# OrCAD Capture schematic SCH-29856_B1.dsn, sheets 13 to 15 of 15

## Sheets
13 15 MISC: size C
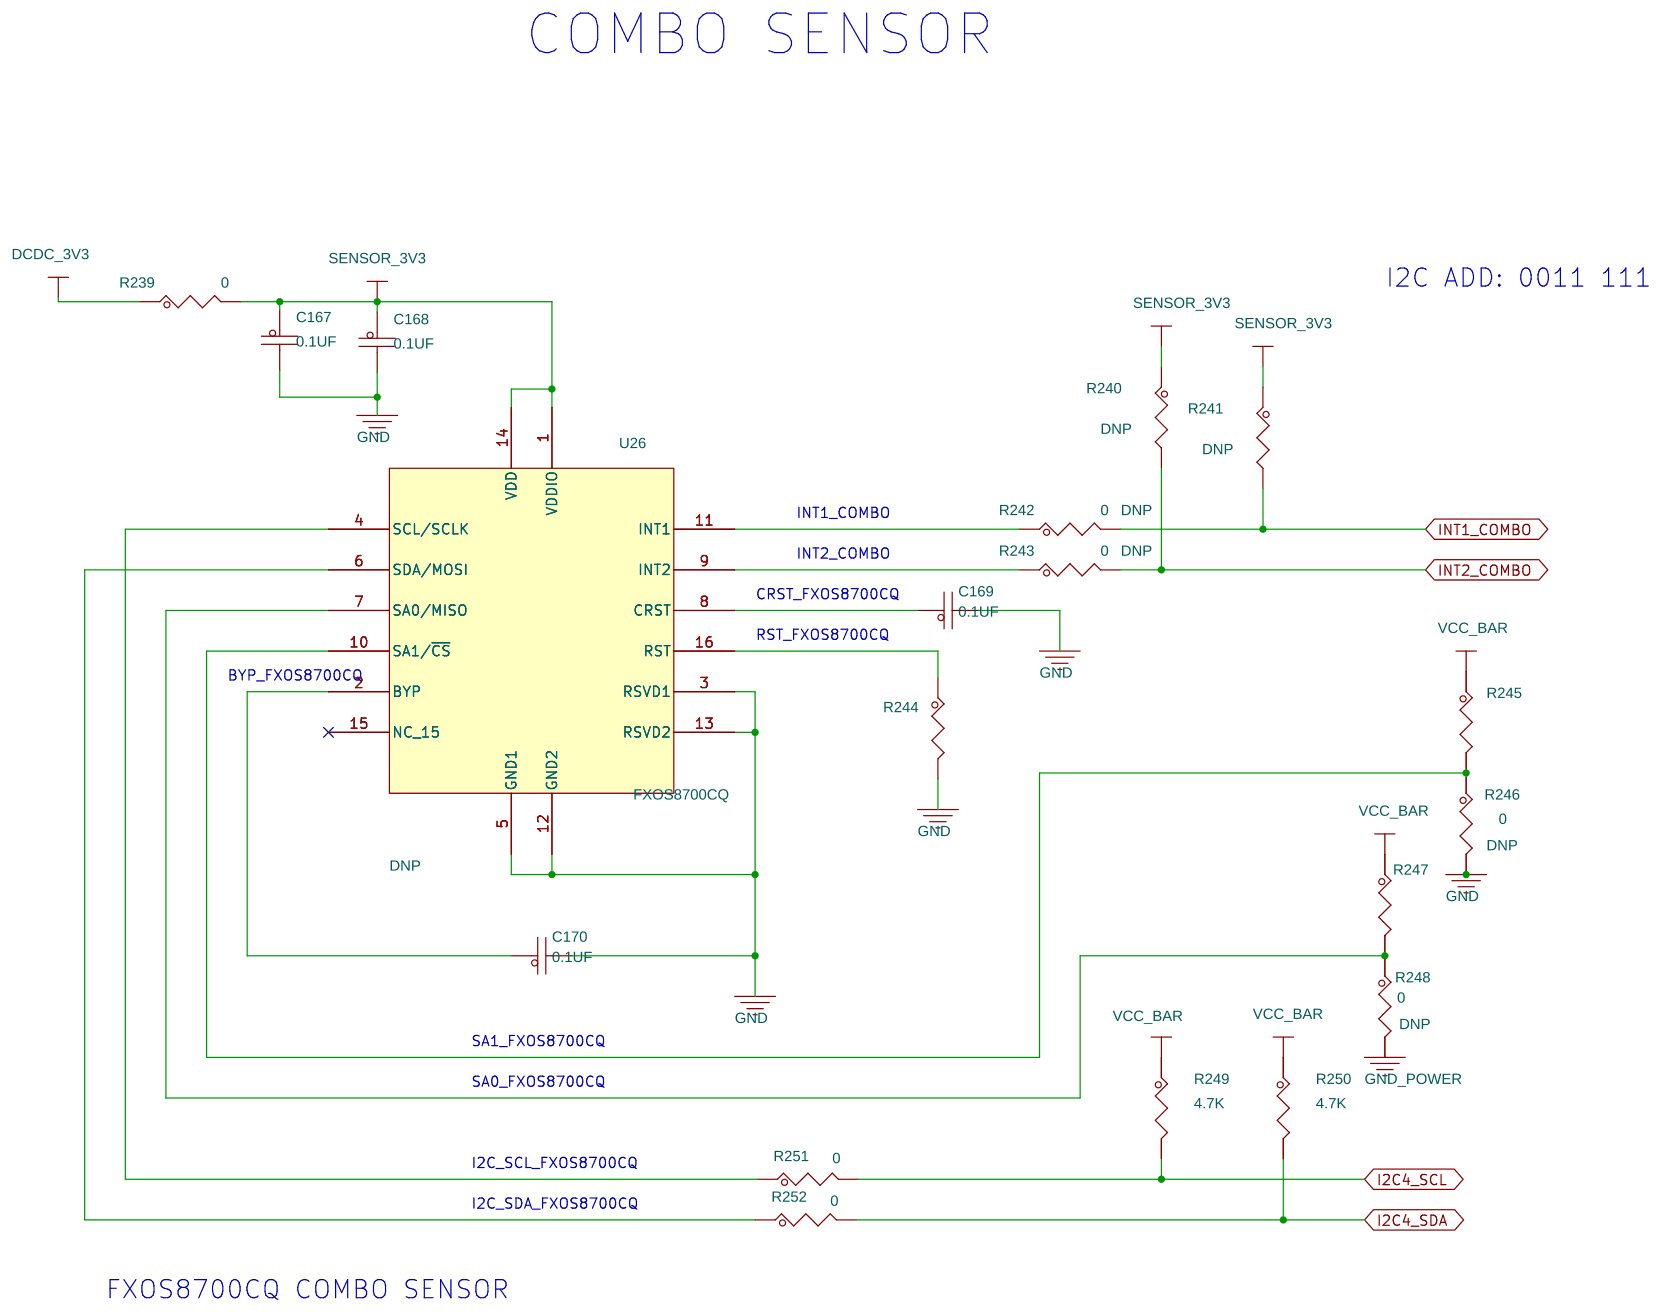
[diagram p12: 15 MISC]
14 10 SD/FLASH: size C
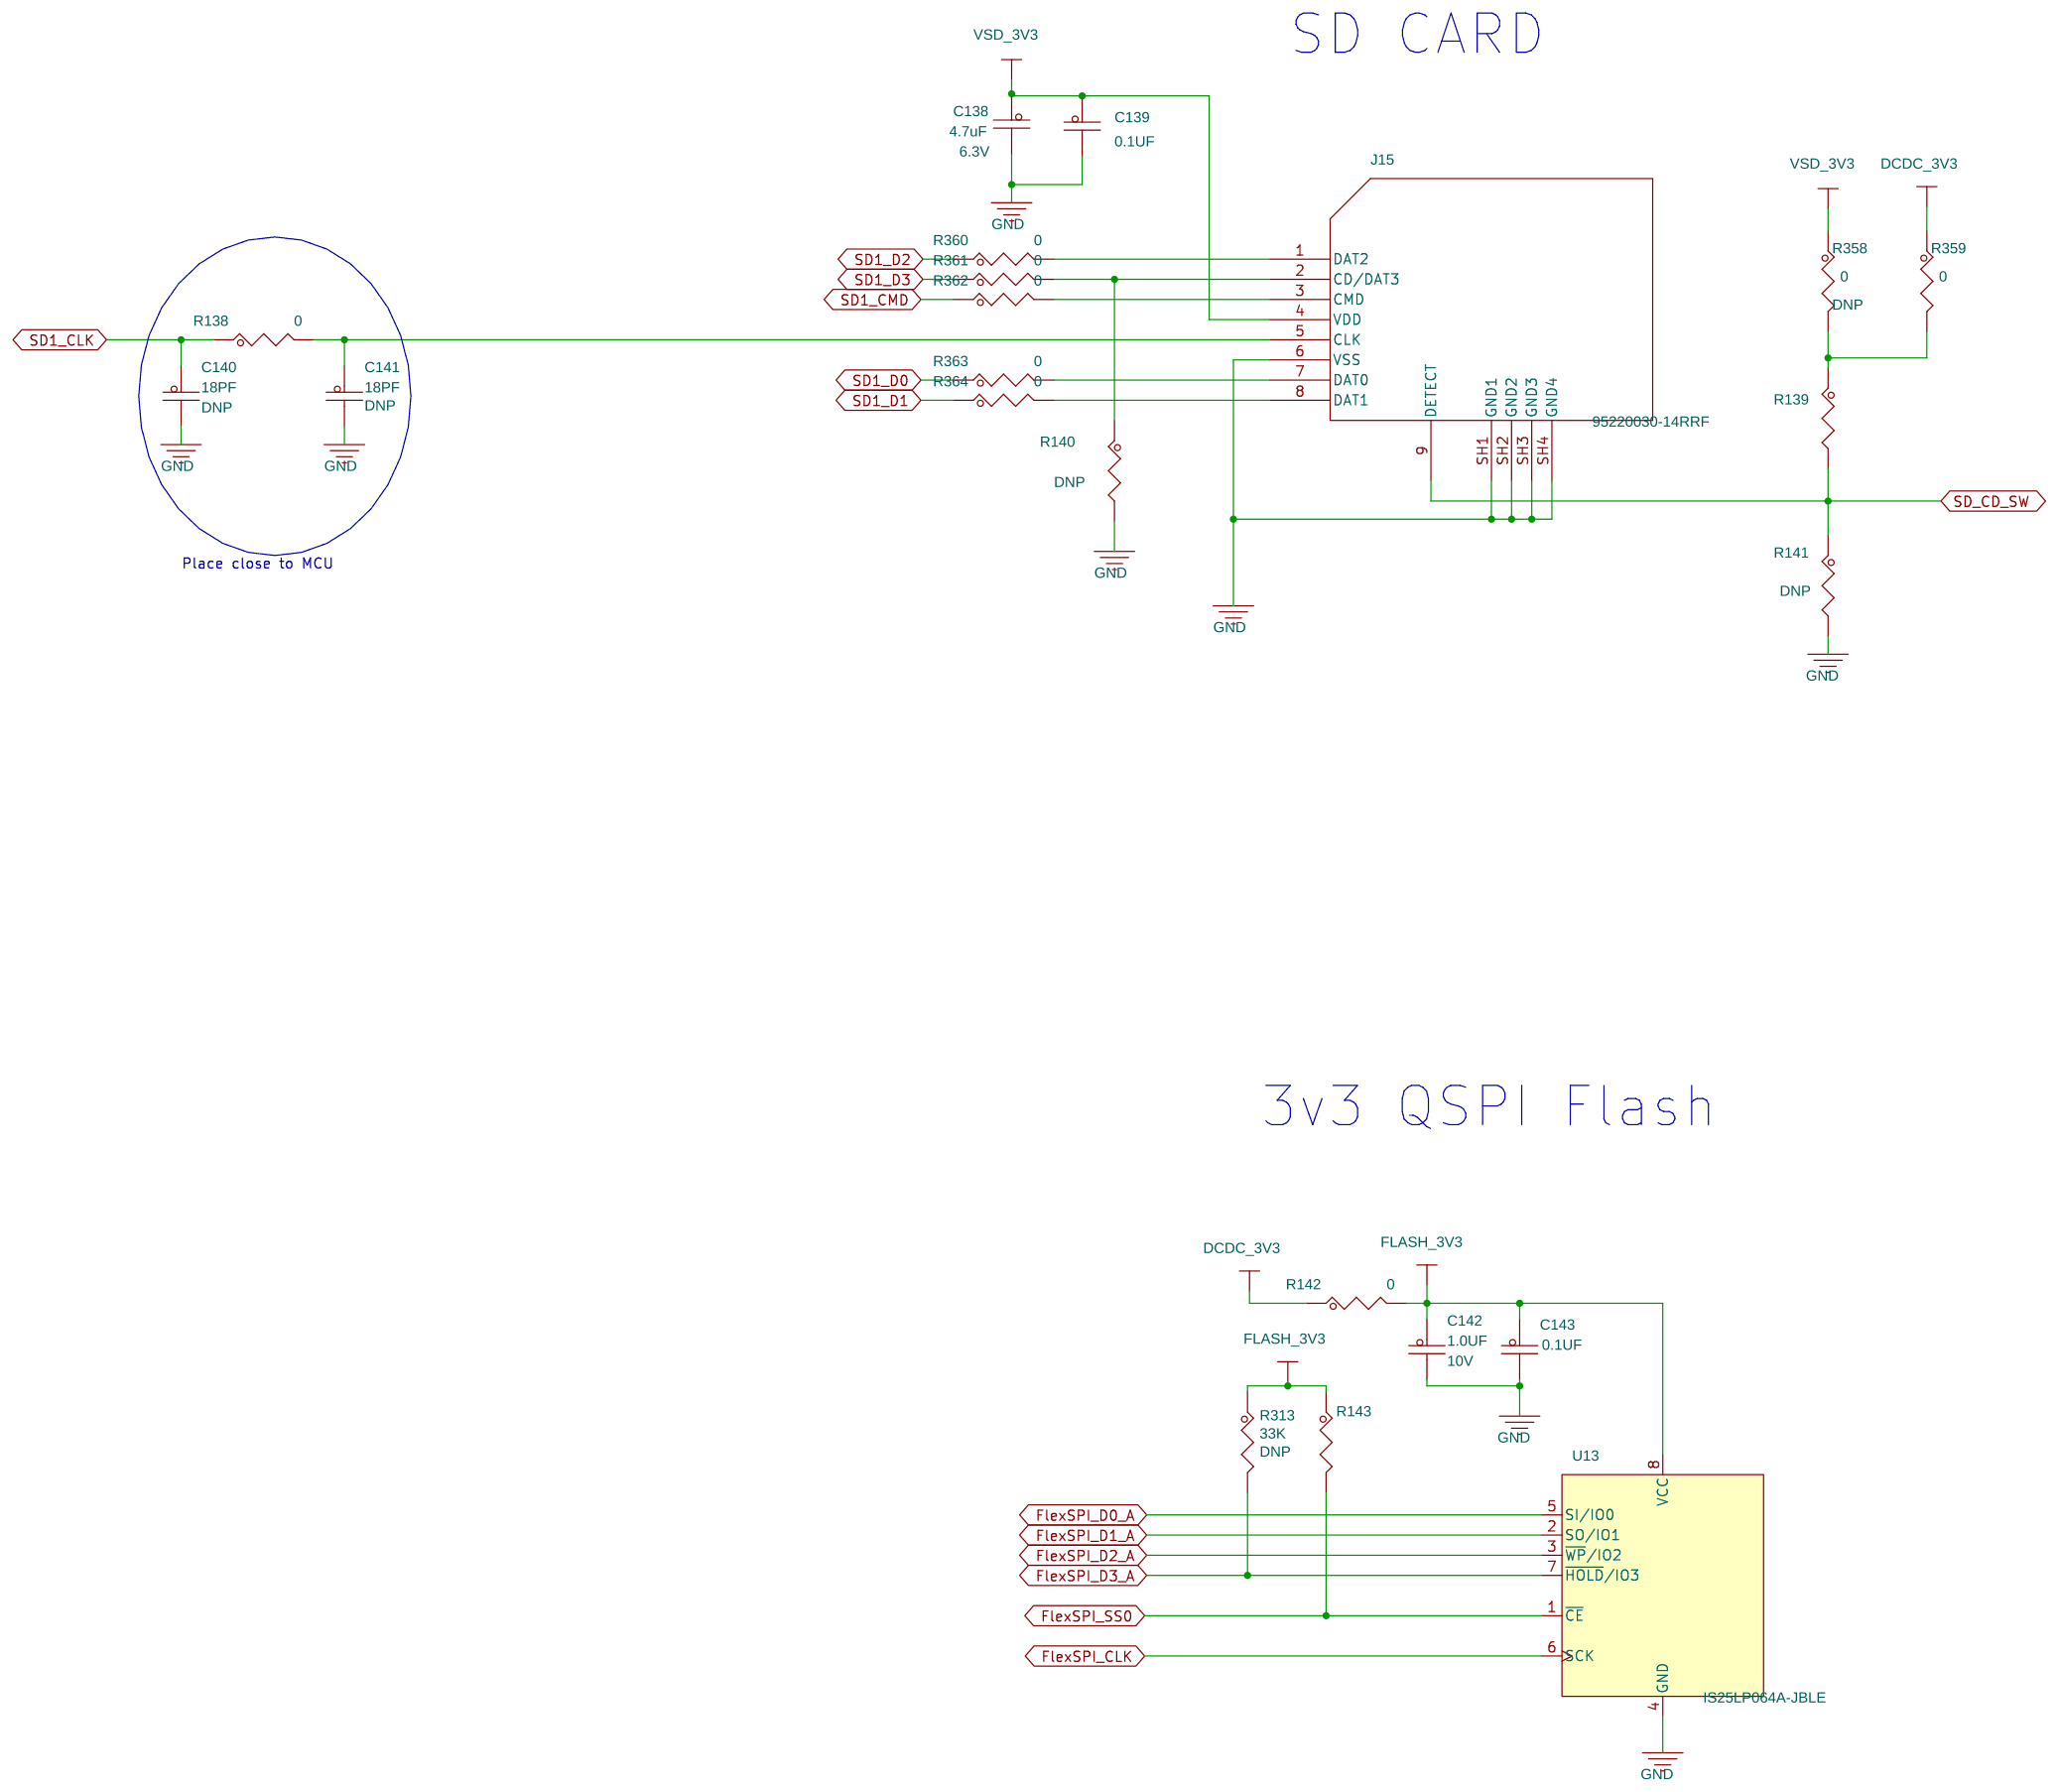
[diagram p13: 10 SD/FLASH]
15 11 ARDUINO/JTAG: size C
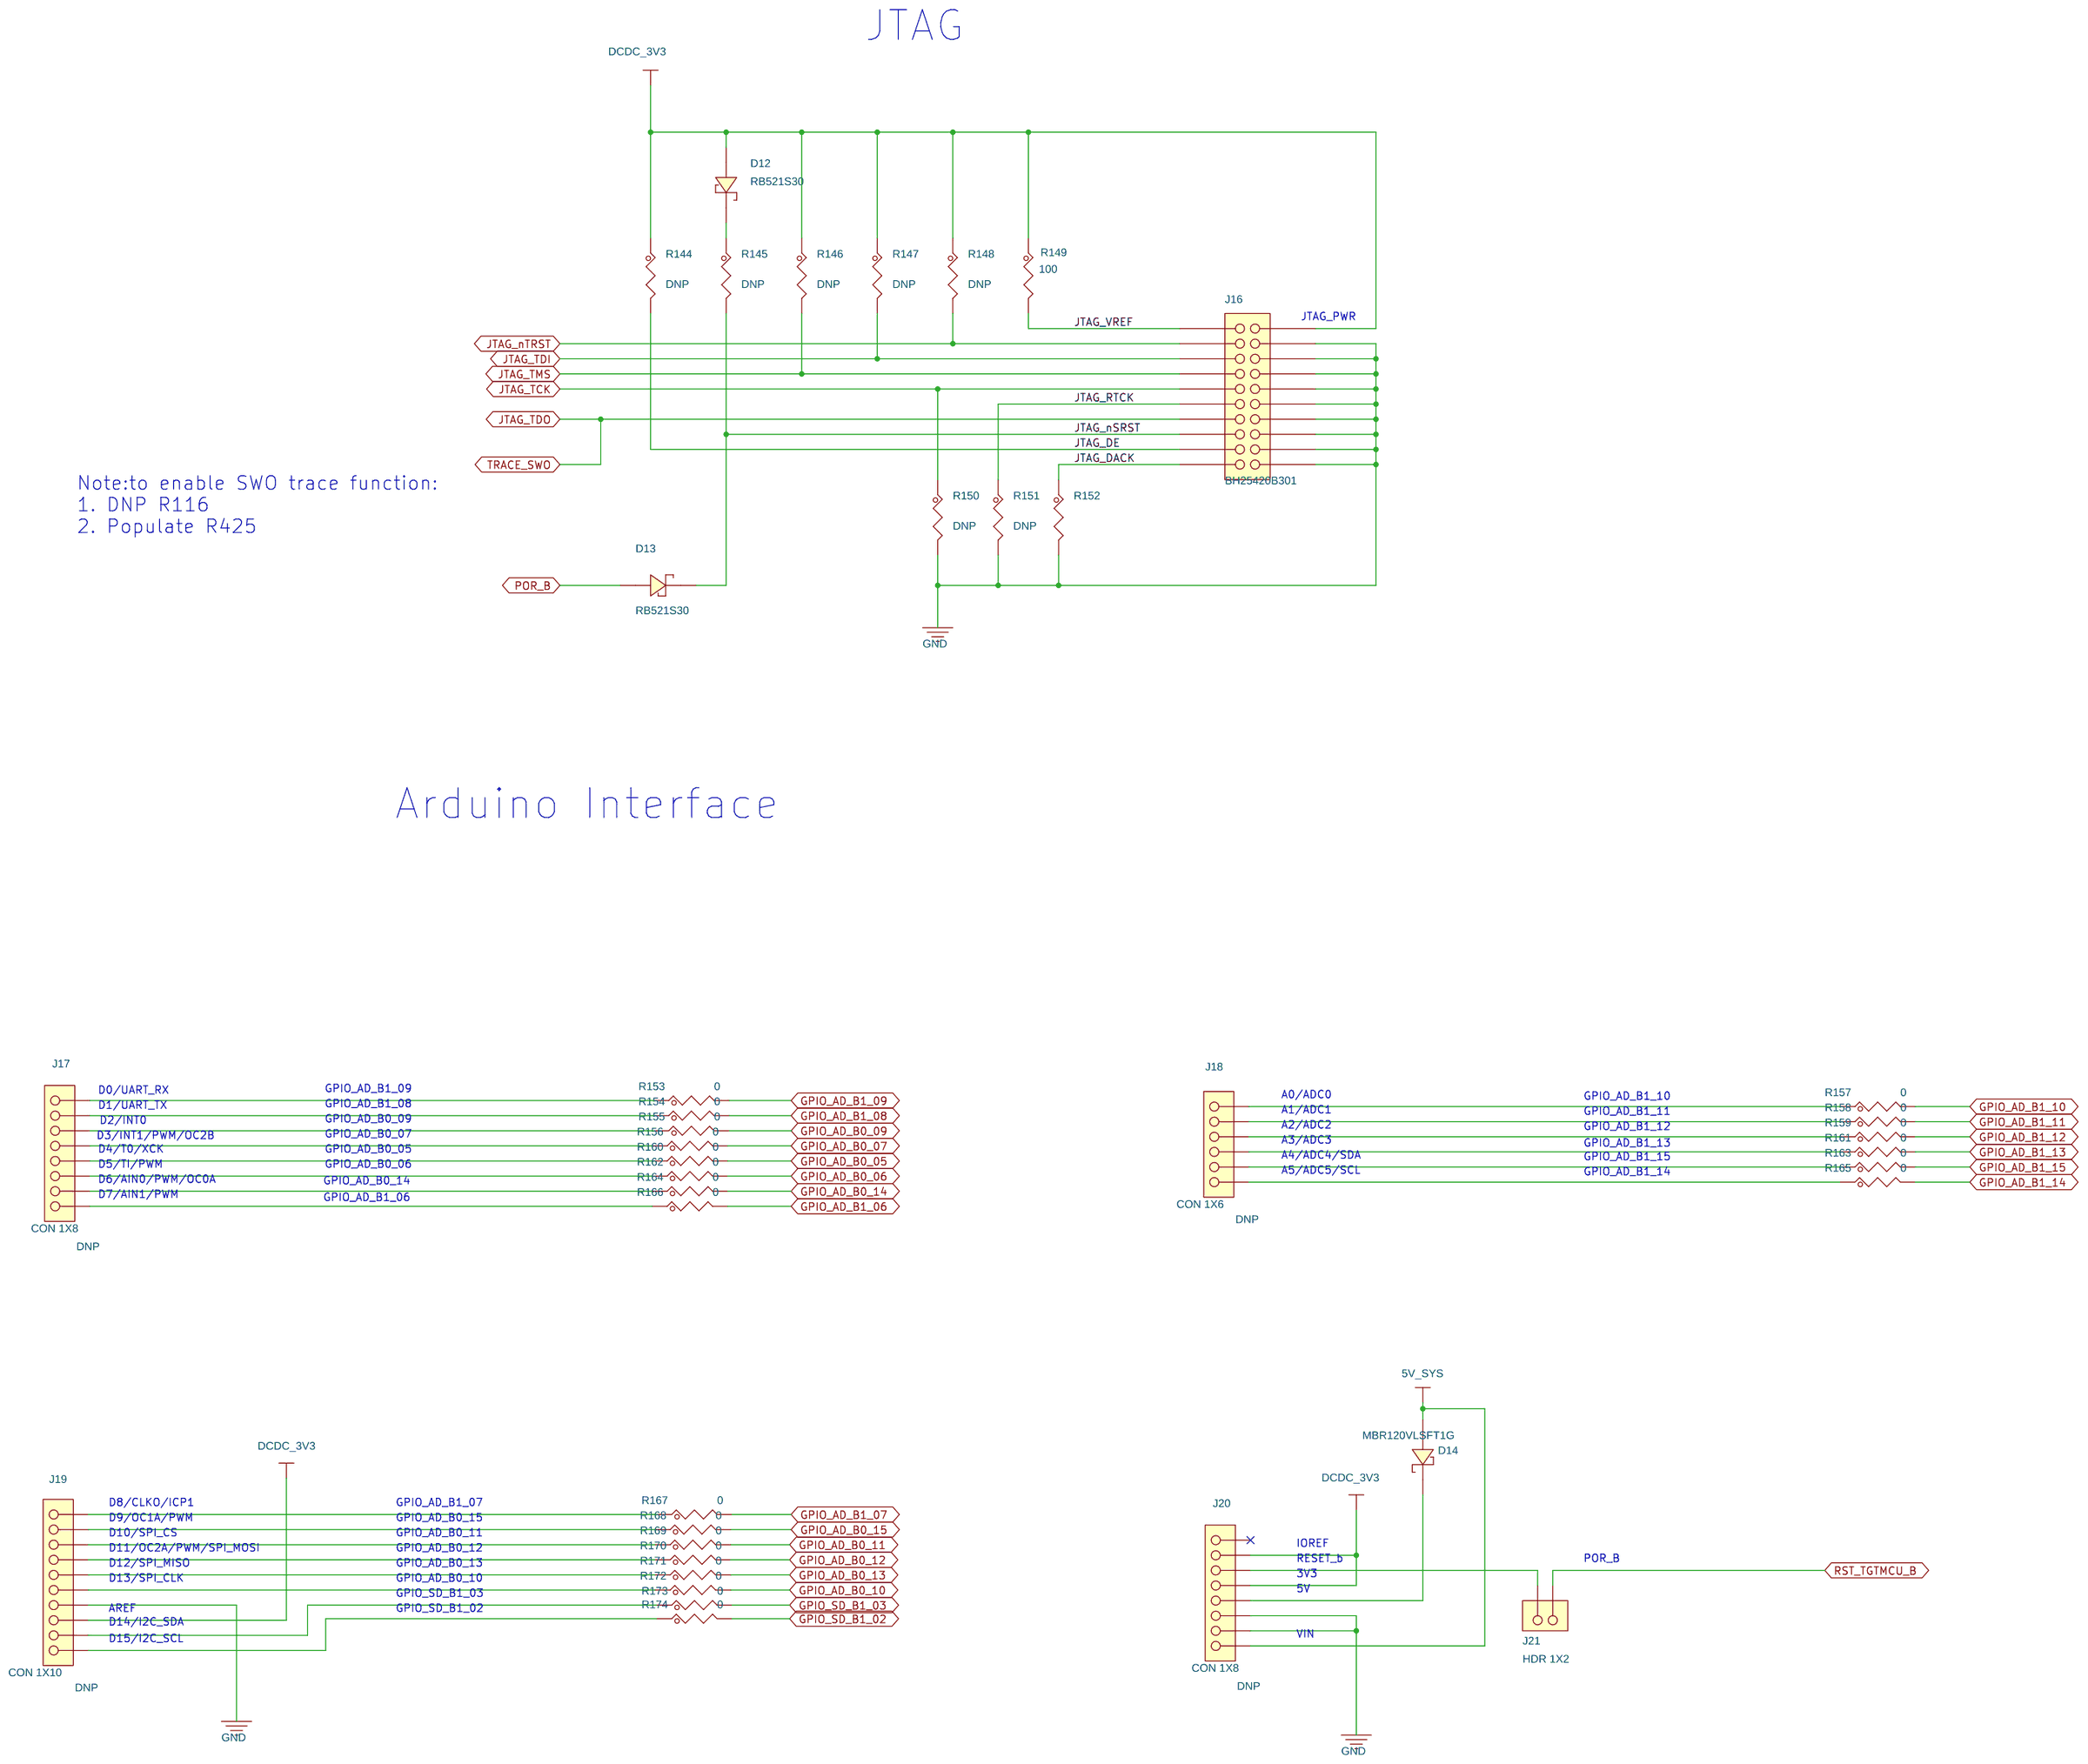
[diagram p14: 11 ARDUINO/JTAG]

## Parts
sheet 10 SD/FLASH
C138  4.7uF  [0402_CC]
C139  0.1UF  [CC0402_25]
C140  18PF  [0402_CC]
C141  18PF  [0402_CC]
C142  1.0UF  [0402_CC]
C143  0.1UF  [CC0402_25]
J15  95220030-14RRF  [CON_SDCARD_95220]
R138  0  [0402_CC]
R139  10K  [0402_CC]
R140  10K  [0402_CC]
R141  10K  [0402_CC]
R142  0  [0402_CC]
R143  10K  [0402_CC]
R313  33K  [RC0402_25]
R358  0  [0402_CC]
R359  0  [0402_CC]
R360  0  [0402_CC]
R361  0  [0402_CC]
R362  0  [0402_CC]
R363  0  [0402_CC]
R364  0  [0402_CC]
U13  IS25LP064A-JBLE  [so8_w]
sheet 11 ARDUINO/JTAG
D12  RB521S30  [SOD523]
D13  RB521S30  [SOD523]
D14  MBR120VLSFT1G  [SOD-123]
J16  BH25420B301  [hdr_2x10m_100_th]
J17  CON 1X8  [con_skt1x8_th]
J18  CON 1X6  [con_skt1x6_th]
J19  CON 1X10  [con_skt1x10_th]
J20  CON 1X8  [con_skt1x8_th]
J21  HDR 1X2  [HDR102]
R144  10K  [0402_CC]
R145  10K  [0402_CC]
R146  10K  [0402_CC]
R147  10K  [0402_CC]
R148  10K  [0402_CC]
R149  100  [0402_CC]
R150  10K  [0402_CC]
R151  10K  [0402_CC]
R152  10K  [0402_CC]
R153  0  [0402_CC]
R154  0  [0402_CC]
R155  0  [0402_CC]
R156  0  [0402_CC]
R157  0  [0402_CC]
R158  0  [0402_CC]
R159  0  [0402_CC]
R160  0  [0402_CC]
R161  0  [0402_CC]
R162  0  [0402_CC]
R163  0  [0402_CC]
R164  0  [0402_CC]
R165  0  [0402_CC]
R166  0  [0402_CC]
R167  0  [0402_CC]
R168  0  [0402_CC]
R169  0  [0402_CC]
R170  0  [0402_CC]
R171  0  [0402_CC]
R172  0  [0402_CC]
R173  0  [0402_CC]
R174  0  [0402_CC]
sheet 15 MISC
C167  0.1UF  [CC0402_25]
C168  0.1UF  [CC0402_25]
C169  0.1UF  [CC0402_25]
C170  0.1UF  [CC0402_25]
R239  0  [0402_CC]
R240  10K  [0402_CC]
R241  10K  [0402_CC]
R242  0  [0402_CC]
R243  0  [0402_CC]
R244  10K  [0402_CC]
R245  10K  [0402_CC]
R246  0  [0402_CC]
R247  10K  [0402_CC]
R248  0  [0402_CC]
R249  4.7K  [RC0402_25]
R250  4.7K  [RC0402_25]
R251  0  [0402_CC]
R252  0  [0402_CC]
U26  FXOS8700CQ  [QFN5X3_0P5_3X3]

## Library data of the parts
C138 = CAP_NP: CAP CER 4.7UF 6.3V 20% X5R 0402; AGILE_PN: 150-78463; CAD_APPROVED: Yes; FPLIST: CC0402_25,CC0402_HD,0402_CC; HEIGHT: 0.65MM; MFG_NAME01: TDK; MFG_PN01: C1005X5R0J475M050BC; ROHS: Yes; Tolerance: 20%; VOLTAGE: 6.3V; voltage rating: 6.3V
C139 C143 C167-C170 = CAP_NP: CAP CER 0.1UF 10V 10% X5R 0402; AGILE_PN: 150-75634; CAD_APPROVED: Yes; FPLIST: CC0402_25,CC0402_HD,0402_CC; HEIGHT: 0.64MM; MFG_NAME01: KEMET; MFG_PN01: C0402C104K8PAC; ROHS: Yes; Tolerance: 10%; VOLTAGE: 10V
C140 C141 = CAP_NP: CAP CER 18PF 50V 1% C0G 0402; AGILE_PN: 150-76630; ASSY_OPT: DNP; CAD_APPROVED: Yes; FPLIST: CC0402_25,CC0402_HD,0402_CC; HEIGHT: 0.59MM; MFG_NAME01: YAGEO; MFG_PN01: CC0402FRNPO9BN180; PRIORITY_PN: 021-00248; ROHS: Yes; ROOM: ATLAS-AP; Tolerance: 1%; VOLTAGE: 50V
C142 = CAP_NP: CAP CER 1.0UF 10V 10% X5R 0402; AGILE_PN: 150-75772; CAD_APPROVED: Yes; FPLIST: CC0402_25,CC0402_HD,0402_CC; HEIGHT: 0.6MM; MFG_NAME01: YAGEO AMERICA; MFG_PN01: CC0402KRX5R6BB105; ROHS: Yes; VOLTAGE: 10V; voltage rating: 10V
J15 = CON8_SDCARD_DETECT: CON 8 SKT SD/MMC RA SMT 43MIL SP 84H AU; AGILE_PN: 211-80169; CAD_APPROVED: Yes; HEIGHT: 2.13MM; MFG_NAME01: ANYTRONIC CORPORATION LIMITED; ROHS: Yes; Temp_Range: -25C to +85C
R138 R142 R153-R174 R239 R251 R252 R359-R364 = RES: RES MF ZERO OHM 1/16W 5% 0402; AGILE_PN: 470-75394; CAD_APPROVED: Yes; FPLIST: RC0402_25,RC0402_HD,RC0402_X2,0402_CC; HEIGHT: 0.45 MM; MFG_NAME01: ROHM; MFG_PN01: MCR01MZPJ000; ROHS: Yes; Tolerance: 5%
R139 R143 = RES: RES MF 10K 1/16W 5% 0402; AGILE_PN: 470-75557; CAD_APPROVED: Yes; FPLIST: RC0402_25,RC0402_HD,0402_CC; HEIGHT: 0.4 MM; MFG_NAME01: VISHAY INTERTECHNOLOGY; MFG_PN01: CRCW040210K0JNED; ROHS: Yes; TOL: 5%; Tolerance: 5%
R140 R144-R148 R150 R151 R240 R241 = RES: RES MF 10K 1/16W 5% 0402; AGILE_PN: 470-75557; ASSY_OPT: DNP; CAD_APPROVED: Yes; FPLIST: RC0402_25,RC0402_HD,0402_CC; HEIGHT: 0.4 MM; MFG_NAME01: VISHAY INTERTECHNOLOGY; MFG_PN01: CRCW040210K0JNED; ROHS: Yes; Tolerance: 5%
R141 = RES: RES MF 10K 1/16W 5% 0402; AGILE_PN: 470-75557; ASSY_OPT: DNP; CAD_APPROVED: Yes; FPLIST: RC0402_25,RC0402_HD,0402_CC; HEIGHT: 0.4 MM; MFG_NAME01: VISHAY INTERTECHNOLOGY; MFG_PN01: CRCW040210K0JNED; ROHS: Yes; TOL: 5%; Tolerance: 5%
R313 = RES: RES MF 33K  1/16W 1% 0402; AGILE_PN: 470-31004; ASSY_OPT: DNP; CAD_APPROVED: Yes; FPLIST: RC0402_25,RC0402_HD,0402_CC; HEIGHT: 0.40 MM; MFG_NAME01: YAGEO AMERICA; MFG_PN01: RC0402FR-0733KL; ROHS: Yes; Temp_Range: -55°C ~ 155°C; Tolerance: 1%
R242 R243 R246 R248 R358 = RES: RES MF ZERO OHM 1/16W 5% 0402; AGILE_PN: 470-75394; ASSY_OPT: DNP; CAD_APPROVED: Yes; FPLIST: RC0402_25,RC0402_HD,RC0402_X2,0402_CC; HEIGHT: 0.45 MM; MFG_NAME01: ROHM; MFG_PN01: MCR01MZPJ000; ROHS: Yes; Tolerance: 5%
U13 = IS25LP064A_8P: IC MEM FLASH QPI 64Mb 2.7-3.6V SO8W; AGILE_PN: 342-00722; CAD_APPROVED: Yes; HEIGHT: 2.16MM; MFG_NAME01: ISSI; ROHS: Yes; Temp_Range: -40C to +105C
D12 D13 = DIODE_SCHTKY: DIODE SCH RECT 200MA 30V AEC-Q101 SOD-523; AGILE_PN: 480-79672; CAD_APPROVED: Yes; HEIGHT: 0.65MM; MFG_NAME01: NEXPERIA; MFG_PN01: RB521S30,115; ROHS: Yes
D14 = DIODE_SCHTKY: DIODE SCH RECT 1A 20V SMT; AGILE_PN: 480-75997; CAD_APPROVED: Yes; HEIGHT: 1MM; MFG_NAME01: ON SEMICONDUCTOR; ROHS: Yes
J16 = CONN_HDR_10X2: CON 2X10 PLUG SHRD TH 100MIL CTR 366H AU 118L; AGILE_PN: 210-80775; CAD_APPROVED: Yes; HEIGHT: 9.3MM; MFG_NAME01: SHENZHEN ATOM TECHNOLOGY CO.,LTD; ROHS: Yes
J17 J20 = CONN_HDR_8X1: CON 1X8 SKT TH 100MIL SP 343H AU 392L; AGILE_PN: 210-80963; ASSY_OPT: DNP; CAD_APPROVED: Yes; HEIGHT: 8.7MM; MFG_NAME01: Townes Enterprice Co.,Ltd; MFG_PN01: F209-1*08SG1-0A-NH; ROHS: Yes
J18 = CONN_HDR_6X1: CON 1X6 SKT TH 100MIL SP 343H AU 392L; AGILE_PN: 210-80962; ASSY_OPT: DNP; CAD_APPROVED: Yes; HEIGHT: 8.7MM; MFG_NAME01: Townes Enterprice Co.,Ltd; MFG_PN01: F209-1*06SG1-0A-NH; ROHS: Yes
J19 = CONN_HDR_10X1: CON 1X10 SKT TH 100MIL SP 343H AU 392L; AGILE_PN: 210-80964; ASSY_OPT: DNP; CAD_APPROVED: Yes; HEIGHT: 8.7MM; MFG_NAME01: Townes Enterprice Co.,Ltd; MFG_PN01: F209-1*10SG1-0A-NH; ROHS: Yes
J21 = CONN_HDR_2X1: HDR 1X2 TH 100MIL SP 339H AU 98L; AGILE_PN: 210-81490; CAD_APPROVED: Yes; HEIGHT: 8.59MM; MFG_NAME01: ANYTRONIC CORPORATION LIMITED; MFG_PN01: 0901S0202011N9T-31RF; ROHS: Yes; Temp_Range: -55°C to +105°C
R149 = RES: RES MF 100 OHM 1/16W 1% 0402; AGILE_PN: 470-30454; CAD_APPROVED: Yes; FPLIST: RC0402_25,RC0402_HD,0402_CC; HEIGHT: 0.4 MM; MFG_NAME01: THYE MING TECH CO LTD; MFG_PN01: CR-02FL6--100R; ROHS: Yes; Tolerance: 1%
R152 R244 R245 R247 = RES: RES MF 10K 1/16W 5% 0402; AGILE_PN: 470-75557; CAD_APPROVED: Yes; FPLIST: RC0402_25,RC0402_HD,0402_CC; HEIGHT: 0.4 MM; MFG_NAME01: VISHAY INTERTECHNOLOGY; MFG_PN01: CRCW040210K0JNED; ROHS: Yes; Tolerance: 5%
R249 R250 = RES: RES MF 4.7K 1/16W 5% 0402; AGILE_PN: 470-75626; CAD_APPROVED: Yes; FPLIST: RC0402_25,RC0402_HD,0402_CC; HEIGHT: 0.41mm; MFG_NAME01: NIC COMPONENTS CORP; MFG_PN01: NRCL04J472TRF; ROHS: Yes; Tolerance: 5%
U26 = FXOS8700CQ_QFN_16P: IC ACCELEROMETER AND MAGNETOMETER SENSOR 3-AXIS 2.5V QFN16; AGILE_PN: 312-80418; ASSY_OPT: DNP; CAD_APPROVED: Yes; FPLIST: QFN5X3_0P5_3X3,QFN5X3_0P5_3X3_a; HEIGHT: 1.25MM; MFG_NAME01: Freescale Semiconductor; ROHS: Yes

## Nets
5V_SYS: D14.A J20.8 ; also on sheet 3 4 6 7 8
GND: C138.2 C139.2 C140.2 C141.2 C142.2 C143.2 C167.2 C168.2 C169.2 C170.2 J15.6(VSS) J15.SH1(GND1) J15.SH2(GND2) J15.SH3(GND3) J15.SH4(GND4) J16.4 J16.6 J16.8 J16.10 J16.12 J16.14 J16.16 J16.18 J16.20 J19.7 J20.6 J20.7 R140.2 R141.2 R150.2 R151.2 R152.2 R244.2 R246.2 R248.2 U13.4(GND) U26.3(RSVD1) U26.5(GND1) U26.12(GND2) U26.13(RSVD2) ; also on sheet 3 4 5 6 7 8 9 10 11 12
CAN_STBY: R161.2 ; also on sheet 5 7
DCDC_3V3: D12.A J16.2 J19.8 J20.2 J20.4 R142.1 R144.1 R146.1 R147.1 R148.1 R149.1 R239.1 R359.1 ; also on sheet 4 5 6 7 8 9 10 11
ENET_CRS_DV: R169.2 ; also on sheet 5 9
ENET_INT: R166.2 ; also on sheet 5 9
ENET_RST: J16.13 ; also on sheet 5 9 11
ENET_RXD0: R172.2 ; also on sheet 5 9
ENET_RXD1: R155.2 ; also on sheet 5 9
ENET_RXER: R170.2 ; also on sheet 5 9
ENET_TXD0: R164.2 ; also on sheet 5 9
ENET_TXD1: R168.2 ; also on sheet 5 9
ENET_TXEN: R171.2 ; also on sheet 5 9
FLASH_3V3: C142.1 C143.1 R142.2 R143.1 R313.1 U13.8(VCC)
FlexSPI_CLK: U13.6(SCK) ; also on sheet 5
FlexSPI_D0_A: U13.5(SI/IO0) ; also on sheet 5
FlexSPI_D1_A: U13.2(SO/IO1) ; also on sheet 5
FlexSPI_D2_A: U13.3(~{WP}/IO2) ; also on sheet 5
FlexSPI_D3_A: R313.2 U13.7(~{HOLD}/IO3) ; also on sheet 5
FlexSPI_SS0: R143.2 U13.1(~{CE}) ; also on sheet 5
GPIO_AD_B0_05: J16.3 R148.2 R160.2 ; also on sheet 4 5
GPIO_AD_B0_06: R162.2 ; also on sheet 5 11
GPIO_AD_B0_07: R156.2 ; also on sheet 5 11
GPIO_AD_B1_07: R167.2 ; also on sheet 4 5
GPIO_AD_B1_08: R154.2 ; also on sheet 5
GPIO_AD_B1_09: R153.2 ; also on sheet 5
GPIO_AD_B1_10: R157.2 ; also on sheet 5 6
GPIO_AD_B1_11: R158.2 ; also on sheet 5 6
GPIO_AD_B1_12: R159.2 ; also on sheet 5 6
GPIO_AD_B1_14: R165.2 ; also on sheet 5 8
GPIO_AD_B1_15: R163.2 ; also on sheet 5 8
GPIO_SD_B1_02: R174.2 R249.2 R251.2 ; also on sheet 5
GPIO_SD_B1_03: R173.2 R250.2 R252.2 ; also on sheet 5
INT1_COMBO: R241.2 R242.2 ; also on sheet 5
INT2_COMBO: R240.2 R243.2 ; also on sheet 5
JTAG_DACK: J16.19 R152.1
JTAG_DE: J16.17 R144.2
JTAG_nSRST: D13.C J16.15 R145.2
JTAG_RTCK: J16.11 R151.1
JTAG_TCK: J16.9 R150.1 ; also on sheet 5 11
JTAG_TDI: J16.5 R147.2 ; also on sheet 4 5 11
JTAG_TMS: J16.7 R146.2 ; also on sheet 5 11
JTAG_VREF: J16.1 R149.2
POR_B: D13.A J21.1 ; also on sheet 4 11
SD1_CLK: C140.1 R138.1 ; also on sheet 5
SD1_CMD: R362.1 ; also on sheet 5
SD1_D0: R363.1 ; also on sheet 5
SD1_D1: R364.1 ; also on sheet 5
SD1_D2: R360.1 ; also on sheet 5
SD1_D3: R361.1 ; also on sheet 5
SD_CD_SW: J15.9(DETECT) R139.2 R141.1 ; also on sheet 5
SENSOR_3V3: C167.1 C168.1 R239.2 R240.1 R241.1 R245.1 R247.1 R249.1 R250.1 U26.1(VDDIO) U26.14(VDD)
VSD_3V3: C138.1 C139.1 J15.4(VDD) R358.1 ; also on sheet 4
N99838171: D12.C R145.1
N99909350: R247.2 R248.1 U26.7(SA0/MISO)
N99909356: R244.1 U26.16(RST)
N99909379: R252.1 U26.6(SDA/MOSI)
N99909383: R251.1 U26.4(SCL/SCLK)
N99909400: C170.1 U26.2(BYP)
N99909418: C169.1 U26.8(CRST)
N99909466: R243.1 U26.9(INT2)
N99909468: R242.1 U26.11(INT1)
N99909488: R245.2 R246.1 U26.10(SA1/~{CS})
N99916564: J18.5 R163.1
N99916634: J18.6 R165.1
N99916953: J20.3 J21.2
N99916957: D14.C J20.5
N99917118: J19.9 R173.1
N100585007: J15.7(DAT0) R363.2
N100585009: J15.8(DAT1) R364.2
N100585016: J15.1(DAT2) R360.2
N100585038: J15.3(CMD) R362.2
N100585089: J15.2(CD/DAT3) R140.1 R361.2
N100640762: J19.10 R174.1
N100763759: C141.1 J15.5(CLK) R138.2
N100784802: J18.1 R157.1
N100784828: J18.2 R158.1
N100784935: J18.3 R159.1
N100784954: J18.4 R161.1
N101100421: R139.1 R358.2 R359.2
N101471655: J19.1 R167.1
N101471657: J19.2 R168.1
N101471659: J19.6 R172.1
N101471661: J19.3 R169.1
N101471663: J19.5 R171.1
N101471665: J19.4 R170.1
N101505077: J17.5 R160.1
N101505079: J17.3 R155.1
N101505081: J17.6 R162.1
N101505083: J17.8 R166.1
N101505085: J17.7 R164.1
N101505087: J17.4 R156.1
N101505089: J17.2 R154.1
N101505091: J17.1 R153.1

Not connected (* = marked no-connect by the designer): J20 1*; U26 15(NC)*

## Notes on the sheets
sheet 13
- COMBO SENSOR
- I2C ADD: 0011 111
- INT1_COMBO
- INT2_COMBO
- CRST_FXOS8700CQ
- RST_FXOS8700CQ
- BYP_FXOS8700CQ
- SA1_FXOS8700CQ
- SA0_FXOS8700CQ
- I2C_SCL_FXOS8700CQ
- I2C_SDA_FXOS8700CQ
- FXOS8700CQ COMBO SENSOR
sheet 14
- SD CARD
- Place close to MCU
- 3v3 QSPI Flash
sheet 15
- JTAG
- JTAG_PWR
- Note:to enable SWO trace function:
  1. DNP R116
  2. Populate R425
- Arduino Interface
- D0/UART_RX
- GPIO_AD_B1_09
- D1/UART_TX
- GPIO_AD_B1_08
- A0/ADC0
- A1/ADC1
- GPIO_AD_B1_10
- D2/INT0
- GPIO_AD_B0_09
- A2/ADC2
- GPIO_AD_B1_11
- GPIO_AD_B1_12
- D3/INT1/PWM/OC2B
- GPIO_AD_B0_07
- A3/ADC3
- GPIO_AD_B1_13
- D4/T0/XCK
- GPIO_AD_B0_05
- A4/ADC4/SDA
- GPIO_AD_B1_15
- D5/TI/PWM
- D6/AIN0/PWM/OC0A
- GPIO_AD_B0_14
- GPIO_AD_B0_06
- A5/ADC5/SCL
- GPIO_AD_B1_14
- D7/AIN1/PWM
- GPIO_AD_B1_06
- D8/CLKO/ICP1
- GPIO_AD_B1_07
- D9/OC1A/PWM
- GPIO_AD_B0_15
- D10/SPI_CS
- GPIO_AD_B0_11
- D11/OC2A/PWM/SPI_MOSI
- GPIO_AD_B0_12
- IOREF
- D12/SPI_MISO
- GPIO_AD_B0_13
- 3V3
- RESET_b
- POR_B
- D13/SPI_CLK
- GPIO_AD_B0_10
- 5V
- AREF
- GPIO_SD_B1_02
- GPIO_SD_B1_03
- D14/I2C_SDA
- D15/I2C_SCL
- VIN
